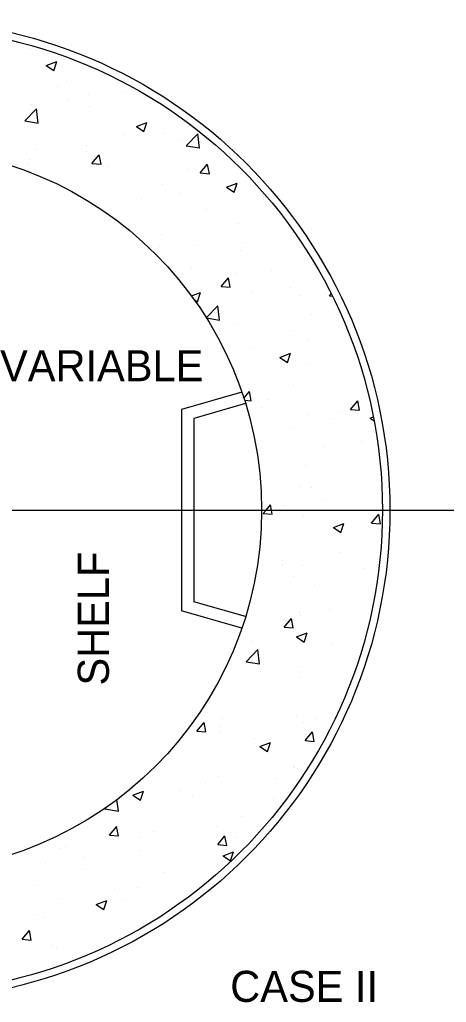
# Model space of a CAD drawing. Extents: x 6712067 to 6713867, y 1867712 to 1869162.
# Drawn here: x 6712658.4 to 6712740.8, y 1867927.1 to 1868116.9 of the extents above; entities that cross this region are included whole.
import ezdxf

# ---------------------------------------------------------------- set-up
doc = ezdxf.new("R2010")
doc.units = 0
doc.layers.add('Misc CnstDet(22)', color=7, linetype='Continuous')

msp = doc.modelspace()

# ---------------------------------------------------------------- linework, layer by layer
at = {"layer": 'Misc CnstDet(22)'}
for p, q in [((6712660.55, 1868111.26), (6712660.55, 1868111.26)), ((6712663.57, 1868108), (6712665.61, 1868108.78)), ((6712663.57, 1868108), (6712665.01, 1868107.03)), ((6712665.01, 1868107.02), (6712665.61, 1868108.78)), ((6712665.77, 1868104.01), (6712665.77, 1868104.01)), ((6712667.54, 1868104.86), (6712667.54, 1868104.86)), ((6712671.66, 1868102.36), (6712671.66, 1868102.36)), ((6712678.94, 1868102.91), (6712678.94, 1868102.91)), ((6712659.44, 1868097.32), (6712661.71, 1868099.68)), ((6712660.62, 1868100.5), (6712660.62, 1868100.5)), ((6712662.03, 1868096.92), (6712661.71, 1868099.68)), ((6712667.9, 1868101.45), (6712667.9, 1868101.45)), ((6712671.92, 1868100.1), (6712671.92, 1868100.1)), ((6712659.44, 1868097.32), (6712662.03, 1868096.92)), ((6712680.96, 1868096.26), (6712683.01, 1868097.04)), ((6712680.96, 1868096.26), (6712682.42, 1868095.29)), ((6712682.41, 1868095.29), (6712683.01, 1868097.04)), ((6712678.67, 1868094.66), (6712678.67, 1868094.66)), ((6712686.45, 1868094.84), (6712686.45, 1868094.84)), ((6712690.55, 1868092.5), (6712692.82, 1868094.86)), ((6712693.13, 1868092.09), (6712692.81, 1868094.86)), ((6712671.31, 1868092.66), (6712671.31, 1868092.66)), ((6712689.69, 1868093.83), (6712689.69, 1868093.83)), ((6712690.55, 1868092.5), (6712693.14, 1868092.1)), ((6712661.67, 1868091.74), (6712661.67, 1868091.74)), ((6712671.28, 1868091.41), (6712671.28, 1868091.41)), ((6712672.39, 1868089.09), (6712673.8, 1868090.77)), ((6712674.14, 1868088.94), (6712673.8, 1868090.77)), ((6712659.97, 1868089.19), (6712659.97, 1868089.19)), ((6712660.24, 1868089.96), (6712660.24, 1868089.96)), ((6712672.39, 1868089.09), (6712674.14, 1868088.94)), ((6712675.54, 1868088.54), (6712675.54, 1868088.54)), ((6712693.3, 1868087.27), (6712694.71, 1868088.94)), ((6712695.05, 1868087.11), (6712694.71, 1868088.93)), ((6712691.1, 1868087.87), (6712691.1, 1868087.87)), ((6712693.3, 1868087.27), (6712695.05, 1868087.11)), ((6712701.06, 1868087.19), (6712701.06, 1868087.19)), ((6712686.09, 1868085.14), (6712686.09, 1868085.14)), ((6712698.36, 1868084.53), (6712700.4, 1868085.31)), ((6712698.36, 1868084.53), (6712699.82, 1868083.55)), ((6712699.82, 1868083.55), (6712700.4, 1868085.31)), ((6712700.36, 1868084.75), (6712700.36, 1868084.75)), ((6712670.96, 1868082.95), (6712670.96, 1868082.95)), ((6712689.32, 1868083.3), (6712689.32, 1868083.3)), ((6712682.02, 1868082.34), (6712682.02, 1868082.34)), ((6712694.46, 1868080.19), (6712694.46, 1868080.19)), ((6712700.7, 1868077.49), (6712700.7, 1868077.49)), ((6712685.74, 1868075.43), (6712685.74, 1868075.43)), ((6712711.1, 1868075.68), (6712711.1, 1868075.68)), ((6712692.69, 1868073.25), (6712692.69, 1868073.25)), ((6712701.45, 1868073.78), (6712701.45, 1868073.78)), ((6712685.42, 1868072.98), (6712685.42, 1868072.98)), ((6712700.98, 1868072.32), (6712700.98, 1868072.32)), ((6712715.07, 1868069.65), (6712715.07, 1868069.65)), ((6712691.57, 1868069.06), (6712691.57, 1868069.06)), ((6712700.35, 1868067.78), (6712700.35, 1868067.78)), ((6712707.12, 1868068.41), (6712707.12, 1868068.41)), ((6712697.35, 1868065.34), (6712698.75, 1868067.01)), ((6712699.09, 1868065.19), (6712698.75, 1868067.01)), ((6712691.6, 1868063.51), (6712693.31, 1868064.18)), ((6712692.73, 1868062.41), (6712693.31, 1868064.18)), ((6712697.35, 1868065.34), (6712699.09, 1868065.19)), ((6712703.43, 1868064.19), (6712703.43, 1868064.19)), ((6712710.73, 1868065.14), (6712710.73, 1868065.14)), ((6712718.25, 1868063.51), (6712718.59, 1868063.9)), ((6712692.08, 1868062.84), (6712692.73, 1868062.41)), ((6712712.58, 1868063.58), (6712712.58, 1868063.58)), ((6712718.25, 1868063.51), (6712718.81, 1868063.46)), ((6712694.45, 1868059.32), (6712696.68, 1868061.64)), ((6712695.58, 1868060.66), (6712695.58, 1868060.66)), ((6712697, 1868058.87), (6712696.68, 1868061.64)), ((6712714.72, 1868059.94), (6712714.72, 1868059.94)), ((6712694.48, 1868059.26), (6712697, 1868058.87)), ((6712699.99, 1868058.08), (6712699.99, 1868058.08)), ((6712710.73, 1868056.85), (6712710.73, 1868056.85)), ((6712714.1, 1868055.1), (6712714.1, 1868055.1)), ((6712703.06, 1868053.65), (6712703.06, 1868053.65)), ((6712708.67, 1868051.66), (6712710.71, 1868052.44)), ((6712710.13, 1868050.68), (6712710.71, 1868052.44)), ((6712708.67, 1868051.66), (6712710.13, 1868050.68)), ((6712714.36, 1868050.24), (6712714.36, 1868050.24)), ((6712701.32, 1868044.93), (6712689.69, 1868041.6)), ((6712701.71, 1868043.78), (6712702.8, 1868045.09)), ((6712703.14, 1868043.26), (6712702.79, 1868045.08)), ((6712711.38, 1868046.19), (6712711.38, 1868046.19)), ((6712724.84, 1868046.03), (6712724.84, 1868046.03)), ((6712702.05, 1868042.72), (6712692.03, 1868039.85)), ((6712701.84, 1868043.37), (6712703.14, 1868043.26)), ((6712706.43, 1868043.6), (6712706.43, 1868043.6)), ((6712722.3, 1868041.58), (6712723.7, 1868043.26)), ((6712724.05, 1868041.43), (6712723.7, 1868043.26)), ((6712689.69, 1868041.6), (6712689.69, 1868002.69)), ((6712705.06, 1868041.96), (6712705.06, 1868041.96)), ((6712720.63, 1868041.29), (6712720.63, 1868041.29)), ((6712722.3, 1868041.58), (6712724.05, 1868041.43)), ((6712692.03, 1868039.85), (6712692.03, 1868004.46)), ((6712714.02, 1868040.54), (6712714.02, 1868040.54)), ((6712718.36, 1868039.79), (6712718.36, 1868039.79)), ((6712726.08, 1868039.92), (6712726.7, 1868040.16)), ((6712726.08, 1868039.92), (6712726.85, 1868039.4)), ((6712711.2, 1868038.05), (6712711.2, 1868038.05)), ((6712726.77, 1868037.38), (6712726.77, 1868037.38)), ((6712724.47, 1868035.49), (6712724.47, 1868035.49)), ((6712717.17, 1868034.53), (6712717.17, 1868034.53)), ((6712713.66, 1868030.84), (6712713.66, 1868030.84)), ((6712712.49, 1868026.67), (6712712.49, 1868026.67)), ((6712714.82, 1868026.48), (6712714.82, 1868026.48)), ((6712716.8, 1868024), (6712716.8, 1868024)), ((6712727.84, 1868025.44), (6712727.84, 1868025.44)), ((6712515.6, 1868022.15), (6712754.77, 1868022.15)), ((6712705.44, 1868021.49), (6712705.99, 1868022.15)), ((6712705.99, 1868022.15), (6712706.84, 1868023.16)), ((6712707.03, 1868022.15), (6712706.84, 1868023.16)), ((6712707.18, 1868021.34), (6712707.03, 1868022.15)), ((6712709.51, 1868023.03), (6712709.51, 1868023.03)), ((6712728.44, 1868023.32), (6712728.44, 1868023.32)), ((6712705.44, 1868021.49), (6712707.18, 1868021.34)), ((6712713.3, 1868021.13), (6712713.3, 1868021.13)), ((6712726.34, 1868019.66), (6712727.75, 1868021.34)), ((6712728.08, 1868019.5), (6712727.75, 1868021.32)), ((6712718.98, 1868018.78), (6712721.02, 1868019.57)), ((6712718.98, 1868018.78), (6712720.43, 1868017.8)), ((6712720.43, 1868017.8), (6712721.02, 1868019.57)), ((6712726.34, 1868019.66), (6712728.08, 1868019.5)), ((6712709.14, 1868012.5), (6712709.14, 1868012.5)), ((6712720.18, 1868013.95), (6712720.18, 1868013.95)), ((6712709.15, 1868011.58), (6712709.15, 1868011.58)), ((6712712.95, 1868011.43), (6712712.95, 1868011.43)), ((6712724.71, 1868010.93), (6712724.71, 1868010.93)), ((6712711.3, 1868009.29), (6712711.3, 1868009.29)), ((6712715.29, 1868007.67), (6712715.29, 1868007.67)), ((6712702.05, 1868001.59), (6712692.03, 1868004.46)), ((6712718.27, 1868002.88), (6712718.27, 1868002.88)), ((6712701.32, 1867999.36), (6712689.69, 1868002.69)), ((6712709.48, 1867999.55), (6712710.88, 1868001.23)), ((6712711.23, 1867999.41), (6712710.88, 1868001.23)), ((6712712.5, 1868002.46), (6712712.5, 1868002.46)), ((6712712.59, 1868001.72), (6712712.59, 1868001.72)), ((6712709.48, 1867999.55), (6712711.23, 1867999.41)), ((6712711.89, 1867997.65), (6712713.92, 1867998.43)), ((6712711.89, 1867997.65), (6712713.34, 1867996.66)), ((6712713.34, 1867996.66), (6712713.92, 1867998.43)), ((6712703.34, 1867996.77), (6712703.34, 1867996.77)), ((6712718.9, 1867996.11), (6712718.9, 1867996.11)), ((6712702.14, 1867992.84), (6712704.41, 1867995.21)), ((6712704.73, 1867992.43), (6712704.41, 1867995.21)), ((6712723.24, 1867993.38), (6712723.24, 1867993.38)), ((6712702.14, 1867992.84), (6712704.73, 1867992.44)), ((6712712.24, 1867992.03), (6712712.24, 1867992.03)), ((6712697.51, 1867990.16), (6712697.51, 1867990.16)), ((6712704.83, 1867990.96), (6712704.83, 1867990.96)), ((6712712.41, 1867989.77), (6712712.41, 1867989.77)), ((6712711.88, 1867982.32), (6712711.88, 1867982.32)), ((6712692.62, 1867979.46), (6712694.02, 1867981.14)), ((6712694.36, 1867979.31), (6712694.02, 1867981.14)), ((6712697.16, 1867980.45), (6712697.16, 1867980.45)), ((6712697.67, 1867981.87), (6712697.67, 1867981.87)), ((6712713.23, 1867981.22), (6712713.23, 1867981.22)), ((6712715.58, 1867981.88), (6712715.58, 1867981.88)), ((6712692.62, 1867979.46), (6712694.36, 1867979.31)), ((6712697.17, 1867979.46), (6712697.17, 1867979.46)), ((6712713.52, 1867977.64), (6712714.93, 1867979.31)), ((6712715.27, 1867977.48), (6712714.93, 1867979.31)), ((6712703.81, 1867977.96), (6712703.81, 1867977.96)), ((6712704.8, 1867976.51), (6712706.83, 1867977.29)), ((6712704.8, 1867976.51), (6712706.25, 1867975.52)), ((6712706.25, 1867975.52), (6712706.83, 1867977.29)), ((6712713.52, 1867977.64), (6712715.27, 1867977.49)), ((6712711.53, 1867972.61), (6712711.53, 1867972.61)), ((6712696.8, 1867970.75), (6712696.8, 1867970.75)), ((6712711.2, 1867972.37), (6712711.2, 1867972.37)), ((6712681.84, 1867968.7), (6712681.84, 1867968.7)), ((6712694.21, 1867969.45), (6712694.21, 1867969.45)), ((6712707.91, 1867970.38), (6712707.91, 1867970.38)), ((6712680.3, 1867967.1), (6712682.34, 1867967.89)), ((6712680.3, 1867967.1), (6712681.76, 1867966.13)), ((6712681.76, 1867966.13), (6712682.34, 1867967.89)), ((6712689.5, 1867967.96), (6712689.5, 1867967.96)), ((6712691.88, 1867967.05), (6712691.88, 1867967.05)), ((6712677.49, 1867964.04), (6712677.22, 1867966.24)), ((6712678.46, 1867966.52), (6712678.46, 1867966.52)), ((6712707.43, 1867966.4), (6712707.43, 1867966.4)), ((6712674.89, 1867964.44), (6712675.22, 1867964.77)), ((6712674.89, 1867964.44), (6712677.49, 1867964.04)), ((6712701.19, 1867963.05), (6712701.19, 1867963.05)), ((6712675.75, 1867959.37), (6712677.17, 1867961.04)), ((6712675.75, 1867959.37), (6712677.5, 1867959.22)), ((6712677.5, 1867959.22), (6712677.15, 1867961.04)), ((6712684.19, 1867960.13), (6712684.19, 1867960.13)), ((6712696.46, 1867961.04), (6712696.46, 1867961.04)), ((6712696.66, 1867957.54), (6712698.06, 1867959.22)), ((6712698.41, 1867957.38), (6712698.06, 1867959.21)), ((6712681.48, 1867958.99), (6712681.48, 1867958.99)), ((6712696.66, 1867957.54), (6712698.41, 1867957.38)), ((6712700.24, 1867958.9), (6712700.24, 1867958.9)), ((6712666.34, 1867956.81), (6712666.34, 1867956.81)), ((6712667.19, 1867957.22), (6712667.19, 1867957.22)), ((6712681.84, 1867956.46), (6712681.84, 1867956.46)), ((6712697.71, 1867955.37), (6712699.74, 1867956.15)), ((6712699.15, 1867954.39), (6712699.74, 1867956.15)), ((6712663.5, 1867954.05), (6712663.5, 1867954.05)), ((6712670.8, 1867955.02), (6712670.8, 1867955.02)), ((6712697.71, 1867955.37), (6712699.15, 1867954.4)), ((6712670.64, 1867952.82), (6712670.64, 1867952.82)), ((6712686.2, 1867952.16), (6712686.2, 1867952.16)), ((6712661.23, 1867949.57), (6712661.23, 1867949.57)), ((6712676.79, 1867948.9), (6712676.79, 1867948.9)), ((6712681.14, 1867949.29), (6712681.14, 1867949.29)), ((6712665.99, 1867947.1), (6712665.99, 1867947.1)), ((6712673.21, 1867945.97), (6712675.25, 1867946.75)), ((6712673.21, 1867945.97), (6712674.66, 1867944.99)), ((6712674.66, 1867944.99), (6712675.25, 1867946.75)), ((6712678.33, 1867947.02), (6712678.33, 1867947.02)), ((6712661.33, 1867944.09), (6712661.33, 1867944.09)), ((6712674.16, 1867944.97), (6712674.16, 1867944.97)), ((6712663.12, 1867943.52), (6712663.12, 1867943.52)), ((6712658.9, 1867939.27), (6712660.3, 1867940.95)), ((6712660.63, 1867939.11), (6712660.3, 1867940.95)), ((6712658.9, 1867939.27), (6712660.64, 1867939.12)), ((6712664.84, 1867938.01), (6712664.84, 1867938.01)), ((6712665.63, 1867937.4), (6712665.63, 1867937.4))]:
    msp.add_line(p, q, dxfattribs=at)
for radius in [94.73, 93.28, 69.96]:
    msp.add_circle((6712635.18, 1868022.15), radius, dxfattribs=at)

# ---------------------------------------------------------------- texts
for s, p in [('VARIABLE', (6712654.65, 1868047.04)), ('CASE II', (6712699.08, 1867927.17))]:
    msp.add_text(s, height=6, dxfattribs=at).set_placement(p)
msp.add_text('SHELF', height=6, rotation=90, dxfattribs=at).set_placement((6712675.65, 1867988.27))

doc.saveas('drawing.dxf')
